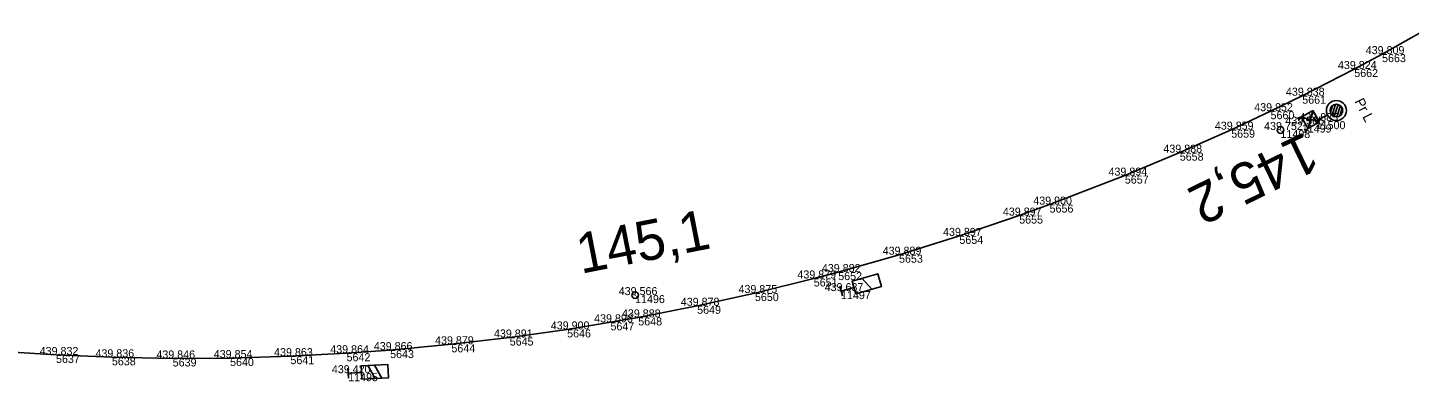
# Model space of a CAD drawing. Extents: x -654154 to -652650, y -1166925 to -1164904.
# Drawn here: x -653058.4 to -652851.3, y -1166918.1 to -1166865.1 of the extents above; entities that cross this region are included whole.
import ezdxf

# ---------------------------------------------------------------- set-up
doc = ezdxf.new("R2010")
doc.units = 0
for name, color, linetype in [('Vrstva 1', 7, 'Continuous'), ('Vrstva 6', 7, 'Continuous'), ('Vrstva 60', 7, 'Continuous'), ('Vrstva 61', 7, 'Continuous'), ('Vrstva 7', 7, 'Continuous')]:
    doc.layers.add(name, color=color, linetype=linetype)

msp = doc.modelspace()

# ---------------------------------------------------------------- linework, layer by layer
at = {"layer": 'Vrstva 1'}
msp.add_lwpolyline([(-653063.79, -1166913.52), (-653054.19, -1166914.15), (-653045.81, -1166914.5), (-653036.69, -1166914.67), (-653028.09, -1166914.61), (-653019.04, -1166914.33), (-653010.62, -1166913.89), (-653004.09, -1166913.42), (-652994.9, -1166912.55), (-652986.16, -1166911.53), (-652977.55, -1166910.32), (-652971.05, -1166909.26), (-652966.88, -1166908.52), (-652958.05, -1166906.78), (-652949.39, -1166904.87), (-652940.57, -1166902.69), (-652936.9, -1166901.73), (-652927.78, -1166899.13), (-652918.73, -1166896.31), (-652909.76, -1166893.27), (-652905.2, -1166891.62), (-652893.92, -1166887.28), (-652885.68, -1166883.84), (-652877.97, -1166880.4), (-652872.07, -1166877.63), (-652867.32, -1166875.31), (-652859.52, -1166871.31), (-652855.35, -1166869.08), (-652848.24, -1166865.11)], dxfattribs=at)
at = {"layer": 'Vrstva 6'}
for p, q in [((-652863.1, -1166877.82), (-652862.77, -1166876.77)), ((-652862.84, -1166878.22), (-652862.32, -1166876.59)), ((-652862.51, -1166878.42), (-652861.93, -1166876.62)), ((-652862.13, -1166878.47), (-652861.6, -1166876.8)), ((-652861.69, -1166878.32), (-652861.33, -1166877.18)), ((-652865.52, -1166878.67), (-652865.07, -1166879.56)), ((-652863.53, -1166878.22), (-652865.3, -1166879.12))]:
    msp.add_line(p, q, dxfattribs=at)
for radius in [1.5, 0.949]:
    msp.add_circle((-652862.2, -1166877.53), radius, dxfattribs=at)
at = {"layer": 'Vrstva 60'}
for p, q in [((-652855.35, -1166869.08), (-652855.35, -1166869.08)), ((-652859.52, -1166871.31), (-652859.52, -1166871.31)), ((-652867.32, -1166875.31), (-652867.32, -1166875.31)), ((-652872.07, -1166877.63), (-652872.07, -1166877.63)), ((-652867.38, -1166879.63), (-652867.38, -1166879.63)), ((-652865.3, -1166879.12), (-652865.3, -1166879.12)), ((-652877.97, -1166880.4), (-652877.97, -1166880.4)), ((-652870.59, -1166880.45), (-652870.59, -1166880.45)), ((-652885.68, -1166883.84), (-652885.68, -1166883.84)), ((-652893.92, -1166887.28), (-652893.92, -1166887.28)), ((-652905.2, -1166891.62), (-652905.2, -1166891.62)), ((-652909.76, -1166893.27), (-652909.76, -1166893.27)), ((-652918.73, -1166896.31), (-652918.73, -1166896.31)), ((-652927.78, -1166899.13), (-652927.78, -1166899.13)), ((-652936.9, -1166901.73), (-652936.9, -1166901.73)), ((-652940.57, -1166902.69), (-652940.57, -1166902.69)), ((-652967.36, -1166905.18), (-652967.36, -1166905.18)), ((-652949.39, -1166904.87), (-652949.39, -1166904.87)), ((-652936.48, -1166904.58), (-652936.48, -1166904.58)), ((-652966.88, -1166908.52), (-652966.88, -1166908.52)), ((-652958.05, -1166906.78), (-652958.05, -1166906.78)), ((-652977.55, -1166910.32), (-652977.55, -1166910.32)), ((-652971.05, -1166909.26), (-652971.05, -1166909.26)), ((-652994.9, -1166912.55), (-652994.9, -1166912.55)), ((-652986.16, -1166911.53), (-652986.16, -1166911.53)), ((-653054.19, -1166914.15), (-653054.19, -1166914.15)), ((-653045.81, -1166914.5), (-653045.81, -1166914.5)), ((-653036.69, -1166914.67), (-653036.69, -1166914.67)), ((-653028.09, -1166914.61), (-653028.09, -1166914.61)), ((-653019.04, -1166914.33), (-653019.04, -1166914.33)), ((-653010.62, -1166913.89), (-653010.62, -1166913.89)), ((-653004.09, -1166913.42), (-653004.09, -1166913.42)), ((-653010.38, -1166916.88), (-653010.38, -1166916.88))]:
    msp.add_line(p, q, dxfattribs=at)
at = {"layer": 'Vrstva 7'}
for p, q in [((-652867.45, -1166878.52), (-652865.73, -1166877.51)), ((-652865.73, -1166877.51), (-652866.44, -1166880.24)), ((-652865.73, -1166877.51), (-652864.72, -1166879.24)), ((-652867.76, -1166878.99), (-652868.01, -1166878.55)), ((-652867.45, -1166878.52), (-652867.89, -1166878.77)), ((-652867.45, -1166878.52), (-652866.44, -1166880.24)), ((-652867.45, -1166878.52), (-652864.72, -1166879.24)), ((-652866.44, -1166880.24), (-652864.72, -1166879.24)), ((-652870.55, -1166880.43), (-652870.64, -1166880.47)), ((-652866.75, -1166880.71), (-652867, -1166880.28)), ((-652866.44, -1166880.24), (-652866.88, -1166880.5)), ((-652936.68, -1166903.86), (-652936.27, -1166905.3)), ((-652933.38, -1166902.66), (-652931.88, -1166904.31)), ((-652967.41, -1166905.19), (-652967.31, -1166905.17)), ((-653010.41, -1166916.13), (-653010.34, -1166917.63)), ((-653007.43, -1166915.73), (-653006.33, -1166917.67)), ((-653005.33, -1166917.62), (-653006.43, -1166915.68))]:
    msp.add_line(p, q, dxfattribs=at)
for points in [[(-652936.48, -1166904.58), (-652934.55, -1166904.03), (-652934.28, -1166904.99), (-652930.43, -1166903.9), (-652930.98, -1166901.97), (-652934.83, -1166903.07), (-652934.55, -1166904.03)], [(-653010.38, -1166916.88), (-653008.38, -1166916.78), (-653008.33, -1166917.78), (-653004.33, -1166917.57), (-653004.44, -1166915.57), (-653008.43, -1166915.78), (-653008.38, -1166916.78)]]:
    msp.add_lwpolyline(points, dxfattribs=at)
for centre in [(-652870.59, -1166880.45), (-652967.36, -1166905.18)]:
    msp.add_circle(centre, 0.5, dxfattribs=at)

# ---------------------------------------------------------------- texts
at = {"layer": 'Vrstva 6'}
msp.add_text('Pr L', height=1.5, rotation=297.1588, dxfattribs=at).set_placement((-652859.51, -1166876.15))
at = {"layer": 'Vrstva 60'}
for s, p in [('5663', (-652855.35, -1166870.28)), ('5662', (-652859.52, -1166872.51)), ('5661', (-652867.32, -1166876.51)), ('5660', (-652872.07, -1166878.83)), ('11499', (-652867.38, -1166880.83)), ('11500', (-652865.3, -1166880.32)), ('5659', (-652877.97, -1166881.6)), ('11498', (-652870.59, -1166881.65)), ('5658', (-652885.68, -1166885.04)), ('5657', (-652893.92, -1166888.48)), ('5656', (-652905.2, -1166892.82)), ('5655', (-652909.76, -1166894.47)), ('5654', (-652918.73, -1166897.51)), ('5653', (-652927.78, -1166900.33)), ('5652', (-652936.9, -1166902.93)), ('5651', (-652940.57, -1166903.89)), ('11496', (-652967.36, -1166906.38)), ('5650', (-652949.39, -1166906.07)), ('11497', (-652936.48, -1166905.78)), ('5648', (-652966.88, -1166909.72)), ('5649', (-652958.05, -1166907.98)), ('5646', (-652977.55, -1166911.52)), ('5647', (-652971.05, -1166910.46)), ('5644', (-652994.9, -1166913.75)), ('5645', (-652986.16, -1166912.74)), ('5637', (-653054.19, -1166915.35)), ('5638', (-653045.81, -1166915.7)), ('5639', (-653036.69, -1166915.87)), ('5640', (-653028.09, -1166915.81)), ('5641', (-653019.04, -1166915.53)), ('5642', (-653010.62, -1166915.09)), ('5643', (-653004.09, -1166914.62)), ('11495', (-653010.38, -1166918.08))]:
    msp.add_text(s, height=1.2, dxfattribs=at).set_placement(p)
at = {"layer": 'Vrstva 61'}
for s, p in [('439.809', (-652857.8, -1166869.08)), ('439.824', (-652861.97, -1166871.31)), ('439.838', (-652869.77, -1166875.31)), ('439.852', (-652874.52, -1166877.63)), ('439.859', (-652880.42, -1166880.4)), ('439.752', (-652873.04, -1166880.45)), ('439.505', (-652869.84, -1166879.63)), ('439.885', (-652867.75, -1166879.12)), ('439.888', (-652888.14, -1166883.84)), ('439.894', (-652896.37, -1166887.28)), ('439.897', (-652912.21, -1166893.27)), ('439.900', (-652907.65, -1166891.62)), ('439.897', (-652921.18, -1166896.31)), ('439.889', (-652930.23, -1166899.13)), ('439.879', (-652943.02, -1166902.69)), ('439.882', (-652939.35, -1166901.73)), ('439.566', (-652969.81, -1166905.18)), ('439.875', (-652951.85, -1166904.87)), ('439.637', (-652938.93, -1166904.58)), ('439.878', (-652960.51, -1166906.78)), ('439.896', (-652973.5, -1166909.26)), ('439.888', (-652969.33, -1166908.52)), ('439.891', (-652988.52, -1166911.53)), ('439.900', (-652980, -1166910.32)), ('439.864', (-653013.07, -1166913.89)), ('439.866', (-653006.54, -1166913.42)), ('439.879', (-652997.35, -1166912.55)), ('439.832', (-653056.64, -1166914.15)), ('439.836', (-653048.27, -1166914.5)), ('439.846', (-653039.14, -1166914.67)), ('439.854', (-653030.54, -1166914.61)), ('439.863', (-653021.49, -1166914.33)), ('439.420', (-653012.83, -1166916.88))]:
    msp.add_text(s, height=1.2, dxfattribs=at).set_placement(p)
at = {"layer": 'Vrstva 7'}
for s, rotation, p in [('145,2', 206.0036, (-652866.87, -1166880.65)), ('145,1', 11.1138, (-652975.48, -1166902))]:
    msp.add_text(s, height=6, rotation=rotation, dxfattribs=at).set_placement(p)

doc.saveas('drawing.dxf')
